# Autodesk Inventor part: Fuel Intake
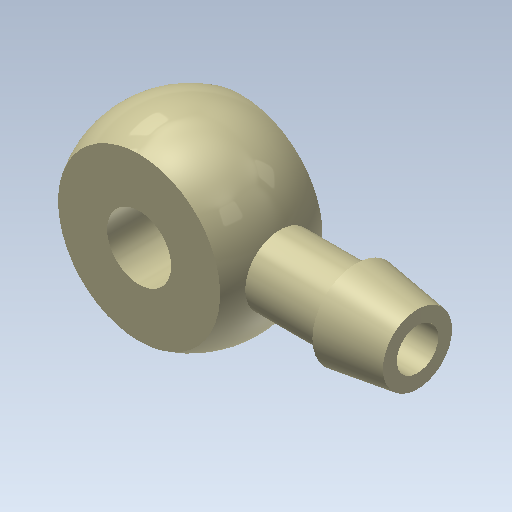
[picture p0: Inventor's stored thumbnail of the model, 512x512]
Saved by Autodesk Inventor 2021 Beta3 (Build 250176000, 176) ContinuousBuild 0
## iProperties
Created: 2012-08
Part Number: Fuel Intake
Material: Nylon, molybdenum disulphide
Document SubType Name: Modeling
Designer: John
Mass: 0.36445 g
Surface Area: 4.27579 cm^2
Volume: 0.322522 cm^3
Density: 1.13 g/cm^3
Appearance: Nylon 6
Author: John
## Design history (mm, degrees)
sketch "Sketch2"
  geometry: L1 (4.75, 0)-(-4.75, 0); A1 r 4.75 centre (0, 0) between (4.75, 0) and (-4.75, 0); 1 further point
  constraints: 2 end point, 2 point on circle, 1 centre point, 1 coincident, 1 midpoint
  dimensions: "d1" = 4.7498 radius of A1
revolve "Revolution1" sketch "Sketch2" stored, may be unused: angle "d0" = 90 deg
sketch "Sketch3"
  geometry: L1 (-4.75, 2.54)-(4.75, 2.54); L2 (4.75, 2.54)-(4.75, -2.54); L3 (4.75, -2.54)-(-4.75, -2.54); L4 (-4.75, -2.54)-(-4.75, 2.54); L5 (0, 0)-(0, 2.54); L6 (-4.75, 2.54)-(4.75, 2.54); L7 (4.75, 2.54)-(4.75, 4.75); L8 (4.75, 4.75)-(-4.75, 4.75); L9 (-4.75, 4.75)-(-4.75, 2.54); L10 (-4.75, -2.54)-(4.75, -2.54); L11 (4.75, -2.54)-(4.75, -4.75); L12 (4.75, -4.75)-(-4.75, -4.75); L13 (-4.75, -4.75)-(-4.75, -2.54); A1 r 4.75 centre (0, 0) between (0, 4.75) and (0, -4.75) reference; A2 r 4.75 centre (0, 0) between (0, -4.75) and (0, 4.75) reference; 1 further point
  constraints: 26 end point, 6 parallel, 3 horizontal, 3 perpendicular, 3 tangent, 2 collinear, 1 midpoint, 1 vertical
  dimensions: "d3" = 5.08 distance of L3.end L1.start; "d5" = 2.54 distance of L5.start L5.end (= 0.5 x d3)
extrude "Extrusion1" cut sketch "Sketch3" stored distance "d6" = 25.4; taper "d7" = 0 deg
sketch "Sketch5"
  geometry: L1 (4.014, -2.54)-(-4.014, -2.54) reference; L2 (-4.014, 2.54)-(4.014, 2.54) reference; L3 (0, 0)-(-18.503, 0); L4 (-11.252, 0)-(-11.252, 1.714); L5 (-11.252, 1.714)-(-8.204, 2.159); L6 (-8.204, 2.159)-(-8.204, 1.714); L7 (-8.204, 1.714)-(-4.43, 1.714); L8 (-4.43, 1.714)-(-4.43, 0); L9 (-11.252, 0)-(-4.43, 0); A1 r 4.75 centre (0, 0) between (-4.014, 2.54) and (-4.014, -2.54) reference; A2 r 4.75 centre (0, 0) between (4.014, -2.54) and (4.014, 2.54) reference; 1 further point
  constraints: 14 end point, 3 perpendicular, 2 parallel, 2 point on line, 1 collinear, 1 horizontal alignment, 1 point on circle
  dimensions: "d12" = 4.0136 horizontal distance of point (0, 0) L1.start (derived); "d15" = 3.429 diameter of L4.end L3; "d16" = 4.318 diameter of L5.end L3; "d17" = 15.2654 distance from line of L1.start L4; "d18" = 12.2174 distance from line of L1.start L6
revolve "Revolution2" sketch "Sketch5" stored, may be unused: angle "d19" = 90 deg
sketch "Sketch6"
  geometry: C1 r 4.014 at (0, 0) reference
hole "Hole1" sketch "Sketch6" at (0, 0) diameter "d20" = 3.175; stored, may be unused: countersink angle "d24" = 82 deg, drill point angle "d26" = 118 deg; dims "d21" = 19.05, "d22" = 9.525, "d23" = 6.35, "d25" = 25.4
sketch "Sketch7"
  geometry: C1 r 1.714 at (0, 0) reference
hole "Hole2" sketch "Sketch7" at (0, 0) diameter "d27" = 2.0574; stored, may be unused: countersink angle "d31" = 82 deg, drill point angle "d33" = 118 deg; dims "d28" = 19.05, "d29" = 3.7084, "d30" = 6.35, "d32" = 25.4
body "Solid1"
node "Project Cut Edges1"
node "Project Cut Edges2"
